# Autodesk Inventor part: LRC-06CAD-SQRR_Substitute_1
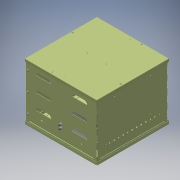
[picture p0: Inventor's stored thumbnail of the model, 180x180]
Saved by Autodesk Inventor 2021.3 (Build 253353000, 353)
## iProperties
Part Number: LRC-06CAD-SQRR_Substitute_1
Material: Generic
Document SubType Name: Modeling
Designer: JChurch
Manufacturer: Standard
Standards Organization: Custom
Density: 1 g/cm^3
Appearance: Smooth - Black
Author: JChurch
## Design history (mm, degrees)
derived "LRC-06CAD-SQRR.iam"
body "Solid9"
node "830376-00-00.iam:1::830376-PAN.ipt:1"
node "830376-00-00.iam:1::830376-FLANGE.ipt:1"
body "Solid10"
node "830376-00-00.iam:1::506010-00-38 SQUEEZED.ipt:1"
body "Solid11"
node "830376-00-00.iam:1::506010-00-38 SQUEEZED.ipt:2"
body "Solid12"
node "830376-00-00.iam:1::506010-00-38 SQUEEZED.ipt:3"
body "Solid13"
node "830376-00-00.iam:1::506010-00-38 SQUEEZED.ipt:4"
body "Solid14"
node "830376-00-00.iam:1::506010-00-38 SQUEEZED.ipt:5"
body "Solid15"
node "830376-00-00.iam:1::506010-00-38 SQUEEZED.ipt:6"
body "Solid16"
node "830376-00-00.iam:1::506010-00-38 SQUEEZED.ipt:7"
body "Solid17"
node "830376-00-00.iam:1::506010-00-38 SQUEEZED.ipt:8"
body "Solid18"
node "830376-00-00.iam:1::830376-FLANGE.ipt:2"
body "Solid19"
node "881035-00-00.iam:1::830505-04-00.ipt:1"
body "Solid20"
node "881035-00-00.iam:1::850014-00-00.iam:1::805044-00-00.ipt:1"
body "Solid21"
node "881035-00-00.iam:1::850014-00-00.iam:1::805174-00-00.ipt:1"
body "Solid22"
node "881035-00-00.iam:1::850014-00-00.iam:1::502055-00-00.ipt:1"
body "Solid23"
node "881035-00-00.iam:1::850014-00-00.iam:1::502055-00-00.ipt:2"
body "Solid24"
node "881035-00-00.iam:1::850014-00-00.iam:1::507032-00-00.ipt:1"
body "Solid25"
node "881035-00-00.iam:1::502099-00-00.ipt:1"
body "Solid26"
node "881035-00-00.iam:1::502099-00-00.ipt:2"
body "Solid27"
node "881035-00-00.iam:1::502099-00-00.ipt:3"
body "Solid28"
node "881035-00-00.iam:1::500027-00-00.ipt:1"
body "Solid29"
node "881035-00-00.iam:1::500027-00-00.ipt:2"
body "Solid30"
node "881035-00-00.iam:1::501030-00-00.ipt:1"
body "Solid31"
node "881035-00-00.iam:1::501030-00-00.ipt:2"
body "Solid32"
node "881035-00-00.iam:1::501030-00-00.ipt:3"
body "Solid33"
node "881035-00-00.iam:1::501030-00-00.ipt:4"
body "Solid34"
node "881035-00-00.iam:1::501030-00-00.ipt:5"
body "Solid35"
node "881035-00-00.iam:1::501030-00-00.ipt:6"
body "Solid36"
node "881035-00-00.iam:1::500027-00-00.ipt:3"
body "Solid37"
node "881035-00-00.iam:1::500027-00-00.ipt:4"
body "Solid38"
node "881035-00-00.iam:1::501030-00-00.ipt:7"
body "Solid39"
node "881035-00-00.iam:1::501030-00-00.ipt:8"
body "Solid40"
node "830402-00-00.ipt:1"
body "Solid41"
node "750055-00-XX.iam:1::507055-00-38_INSTALLED.ipt:1"
body "Solid42"
node "750055-00-XX.iam:1::805338-00-00.ipt:1"
body "Solid43"
node "750055-00-XX.iam:1::805338-01-00.ipt:1"
body "Solid44"
node "750055-00-XX.iam:1::510121-00-00.ipt:1"
body "Solid45"
node "750055-00-XX.iam:1::700466-25-XX (NEW).iam:1::700466-25-XX B"
body "Solid46"
node "750055-00-XX.iam:1::700466-25-XX (NEW).iam:1::700466-25-XX B"
body "Solid47"
node "750055-00-XX.iam:1::700466-25-XX (NEW).iam:1::700466-25-RF.i"
body "Solid48"
node "750055-00-XX.iam:1::700466-25-XX (NEW).iam:1::700466-25-RF1."
body "Solid49"
node "750055-00-XX.iam:1::700466-25-XX (NEW).iam:1::700466-25-RF2."
body "Solid50"
body "Solid51"
node "750055-00-XX.iam:1::700466-25-XX (NEW).iam:1::700466-25-RF2_"
body "Solid52"
node "750055-00-XX.iam:1::507055-00-38_INSTALLED.ipt:2"
body "Solid53"
node "725267-00-00.ipt:1"
body "Solid54"
other parameters: "d15" = 61.595, "d16" = 9.525, "d17" = 9.525, "d35" = 5.08
